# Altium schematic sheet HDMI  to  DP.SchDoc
size A2
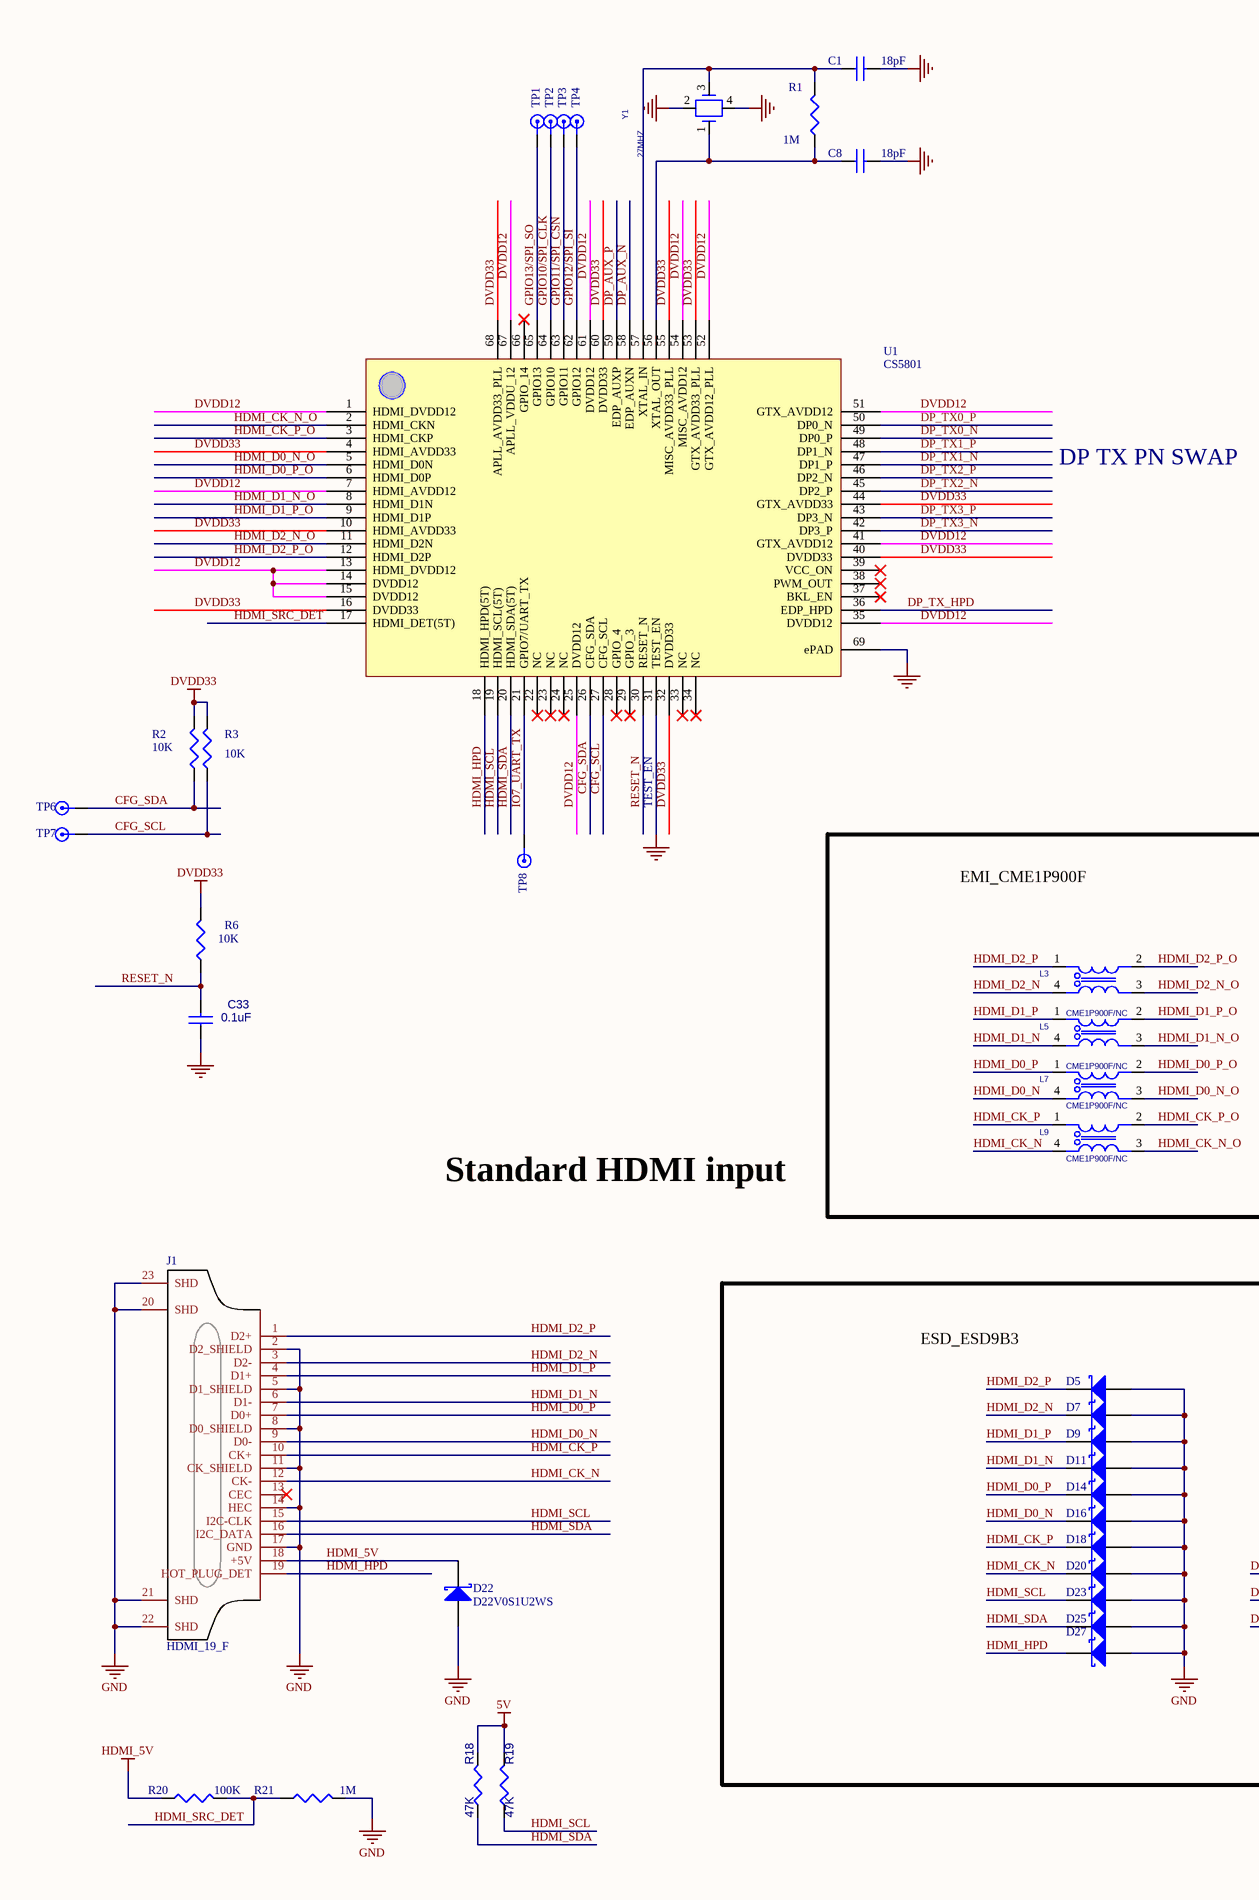
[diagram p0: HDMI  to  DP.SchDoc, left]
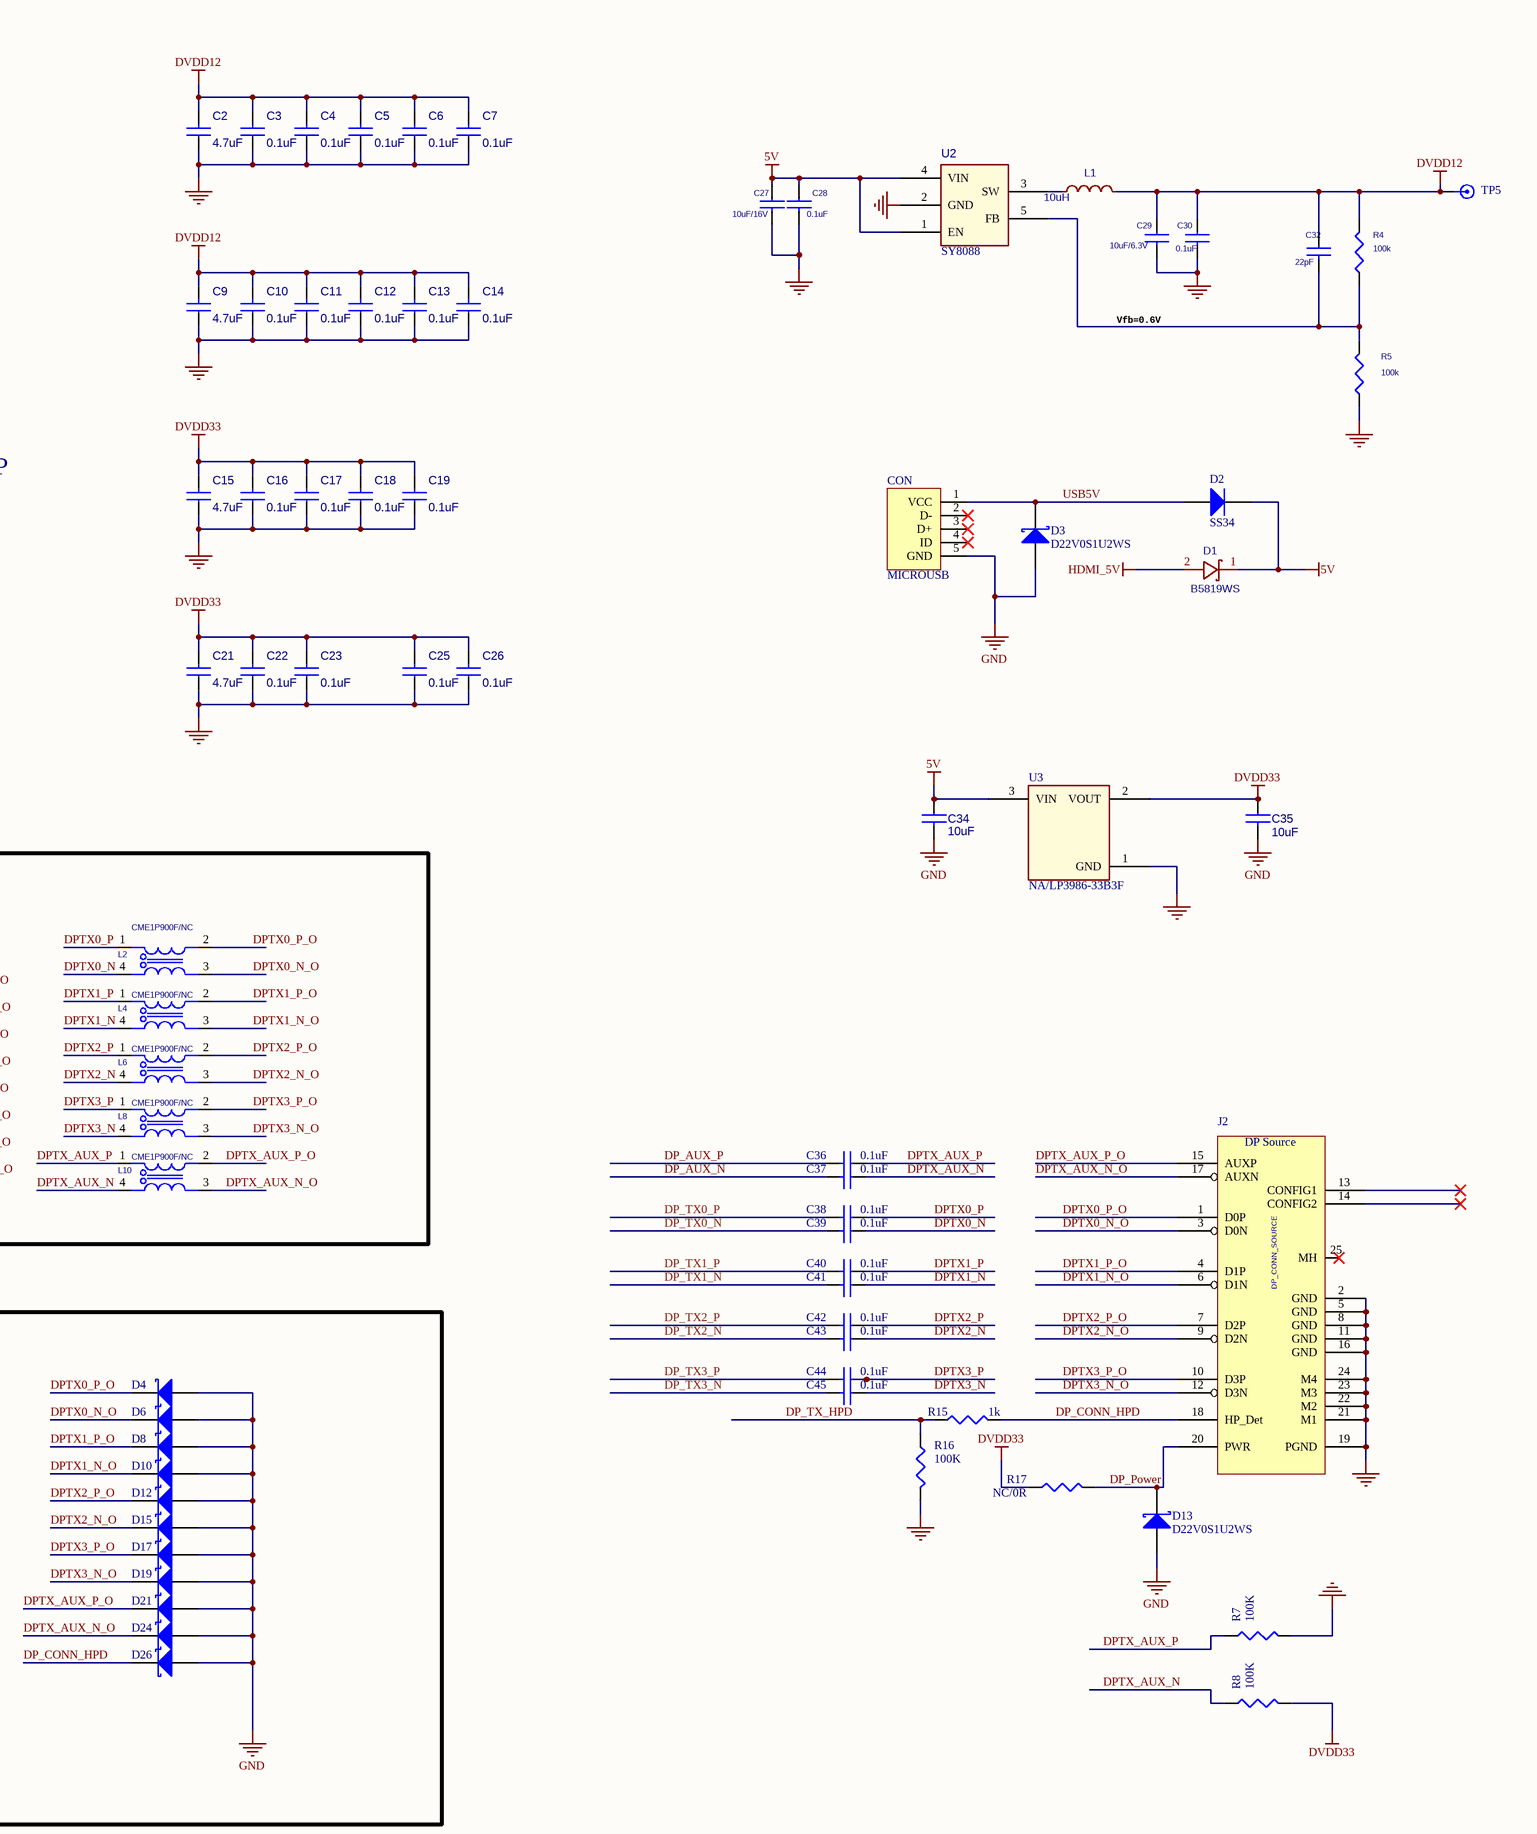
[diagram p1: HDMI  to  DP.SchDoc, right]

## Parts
C1  18pF  [0402/1005 C2]
C2  4.7uF  [0603/1608 C2]
C3  0.1uF  [0402/1005 C2]
C4  0.1uF  [0402/1005 C2]
C5  0.1uF  [0402/1005 C2]
C6  0.1uF  [0402/1005 C2]
C7  0.1uF  [0402/1005 C2]
C8  18pF  [0402/1005 C2]
C9  4.7uF  [0603/1608 C2]
C10  0.1uF  [0402/1005 C2]
C11  0.1uF  [0402/1005 C2]
C12  0.1uF  [0402/1005 C2]
C13  0.1uF  [0402/1005 C2]
C14  0.1uF  [0402/1005 C2]
C15  4.7uF  [0603/1608 C2]
C16  0.1uF  [0402/1005 C2]
C17  0.1uF  [0402/1005 C2]
C18  0.1uF  [0402/1005 C2]
C19  0.1uF  [0402/1005 C2]
C21  4.7uF  [0603/1608 C2]
C22  0.1uF  [0402/1005 C2]
C23  0.1uF  [0402/1005 C2]
C25  0.1uF  [0402/1005 C2]
C26  0.1uF  [0402/1005 C2]
C27  10uF/16V  [0603/1608 C2]
C28  0.1uF  [0402/1005 C2]
C29  10uF/6.3V  [0603/1608 C2]
C30  0.1uF  [0402/1005 C2]
C32  22pF  [0402/1005 C2]
C33  0.1uF  [0402/1005 C2]
C34  10uF  [0603/1608 C2]
C35  10uF  [0603/1608 C2]
C36  0.1uF  [0402/1005 C2]
C37  0.1uF  [0402/1005 C2]
C38  0.1uF  [0402/1005 C2]
C39  0.1uF  [0402/1005 C2]
C40  0.1uF  [0402/1005 C2]
C41  0.1uF  [0402/1005 C2]
C42  0.1uF  [0402/1005 C2]
C43  0.1uF  [0402/1005 C2]
C44  0.1uF  [0402/1005 C2]
C45  0.1uF  [0402/1005 C2]
CON  MICROUSB  [USB-MF-S1-180]
D1  B5819WS  [5819]
D2  SS34  [SMA_L4.4-W2.8-LS5.4-R-RD]
D3  D22V0S1U2WS  [SOD-323]
D4  Diode 18TQ045  [SOD-923_L0.8-W0.6-LS1.0-BI]  (value not drawn)
D5  Diode 18TQ045  [SOD-923_L0.8-W0.6-LS1.0-BI]  (value not drawn)
D6  Diode 18TQ045  [SOD-923_L0.8-W0.6-LS1.0-BI]  (value not drawn)
D7  Diode 18TQ045  [SOD-923_L0.8-W0.6-LS1.0-BI]  (value not drawn)
D8  Diode 18TQ045  [SOD-923_L0.8-W0.6-LS1.0-BI]  (value not drawn)
D9  Diode 18TQ045  [SOD-923_L0.8-W0.6-LS1.0-BI]  (value not drawn)
D10  Diode 18TQ045  [SOD-923_L0.8-W0.6-LS1.0-BI]  (value not drawn)
D11  Diode 18TQ045  [SOD-923_L0.8-W0.6-LS1.0-BI]  (value not drawn)
D12  Diode 18TQ045  [SOD-923_L0.8-W0.6-LS1.0-BI]  (value not drawn)
D13  D22V0S1U2WS  [SOD-923_L0.8-W0.6-LS1.0-BI]
D14  Diode 18TQ045  [SOD-923_L0.8-W0.6-LS1.0-BI]  (value not drawn)
D15  Diode 18TQ045  [SOD-923_L0.8-W0.6-LS1.0-BI]  (value not drawn)
D16  Diode 18TQ045  [SOD-923_L0.8-W0.6-LS1.0-BI]  (value not drawn)
D17  Diode 18TQ045  [SOD-923_L0.8-W0.6-LS1.0-BI]  (value not drawn)
D18  Diode 18TQ045  [SOD-923_L0.8-W0.6-LS1.0-BI]  (value not drawn)
D19  Diode 18TQ045  [SOD-923_L0.8-W0.6-LS1.0-BI]  (value not drawn)
D20  Diode 18TQ045  [SOD-923_L0.8-W0.6-LS1.0-BI]  (value not drawn)
D21  Diode 18TQ045  [SOD-923_L0.8-W0.6-LS1.0-BI]  (value not drawn)
D22  D22V0S1U2WS  [SOD-323]
D23  Diode 18TQ045  [SOD-923_L0.8-W0.6-LS1.0-BI]  (value not drawn)
D24  Diode 18TQ045  [SOD-923_L0.8-W0.6-LS1.0-BI]  (value not drawn)
D25  Diode 18TQ045  [SOD-923_L0.8-W0.6-LS1.0-BI]  (value not drawn)
D26  Diode 18TQ045  [SOD-923_L0.8-W0.6-LS1.0-BI]  (value not drawn)
D27  Diode 18TQ045  [SOD-923_L0.8-W0.6-LS1.0-BI]  (value not drawn)
J1  HDMI_19_F  [HDMI-G]
J2  DP_CONN_SOURCE  [DP-20-J]
L1  10uH  [SWPA252012S]
L2  CME1P900F/NC  [FLT4-0.6-1.3X1.3]
L3  CME1P900F/NC  [FLT4-0.6-1.3X1.3]
L4  CME1P900F/NC  [FLT4-0.6-1.3X1.3]
L5  CME1P900F/NC  [FLT4-0.6-1.3X1.3]
L6  CME1P900F/NC  [FLT4-0.6-1.3X1.3]
L7  CME1P900F/NC  [FLT4-0.6-1.3X1.3]
L8  CME1P900F/NC  [FLT4-0.6-1.3X1.3]
L9  CME1P900F/NC  [FLT4-0.6-1.3X1.3]
L10  CME1P900F/NC  [FLT4-0.6-1.3X1.3]
R1  1M  [0402/1005 R2]
R2  10K  [0402/1005 R2]
R3  10K  [0402/1005 R2]
R4  100k  [0402/1005 R2]
R5  100k  [0402/1005 R2]
R6  10K  [0402/1005 R2]
R7  100K  [0402/1005 R2]
R8  100K  [0402/1005 R2]
R15  1k  [0402/1005 R2]
R16  100K  [0402/1005 R2]
R17  NC/0R  [0402/1005 R2]
R18  47K  [0402/1005 R2]
R19  47K  [0402/1005 R2]
R20  100K  [0402/1005 R2]
R21  1M  [0402/1005 R2]
TP1  TEST_POINT  [PAD]  (value not drawn)
TP2  TEST_POINT  [PAD]  (value not drawn)
TP3  TEST_POINT  [PAD]  (value not drawn)
TP4  TEST_POINT  [PAD]  (value not drawn)
TP5  TEST_POINT  [PAD]  (value not drawn)
TP6  TEST_POINT  [PAD]  (value not drawn)
TP7  TEST_POINT  [PAD]  (value not drawn)
TP8  TEST_POINT  [PAD]  (value not drawn)
U1  CS5801  [QFN68]
U2  SY8088  [SOT23-5L]
U3  NA/LP3986-33B3F  [SOT-123-B]
Y1  27MHZ  [SMD3225]

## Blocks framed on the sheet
EMI_CME1P900F: L2-L10
ESD_ESD9B3: D4-D12 D14-D21 D23-D27

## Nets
5V: C27.1 C28.1 C34.1 D1.1(K) D2.2(K) R18.2 R19.2 U2.1(EN) U2.4(VIN) U3.3(VIN)
DVDD12: C2.2 C3.2 C4.2 C5.2 C6.2 C7.2 C9.2 C10.2 C11.2 C12.2 C13.2 C14.2 C29.1 C30.1 C32.1 L1.2 R4.2 TP5.1 U1.1(HDMI_DVDD12) U1.7(HDMI_AVDD12) U1.13(HDMI_DVDD12) U1.14(DVDD12) U1.15(DVDD12) U1.25(DVDD12) U1.35(DVDD12) U1.41(GTX_AVDD12) U1.51(GTX_AVDD12) U1.52(GTX_AVDD12_PLL) U1.54(MISC_AVDD12) U1.61(DVDD12) U1.67(APLL_VDDU_12)
DVDD33: C15.2 C16.2 C17.2 C18.2 C19.2 C21.2 C22.2 C23.2 C25.2 C26.2 C35.1 R2.1 R3.1 R6.1 R8.2 R17.2 U1.4(HDMI_AVDD33) U1.10(HDMI_AVDD33) U1.16(DVDD33) U1.32(DVDD33) U1.40(DVDD33) U1.44(GTX_AVDD33) U1.53(GTX_AVDD33_PLL) U1.55(MISC_AVDD33_PLL) U1.60(DVDD33) U1.68(APLL_AVDD33_PLL) U3.2(VOUT)
GND: C1.2 C2.1 C3.1 C4.1 C5.1 C6.1 C7.1 C8.2 C9.1 C10.1 C11.1 C12.1 C13.1 C14.1 C15.1 C16.1 C17.1 C18.1 C19.1 C21.1 C22.1 C23.1 C25.1 C26.1 C27.2 C28.2 C29.2 C30.2 C33.1 C34.2 C35.2 CON.5(GND) D3.3(A) D4.3(A) D5.3(A) D6.3(A) D7.3(A) D8.3(A) D9.3(A) D10.3(A) D11.3(A) D12.3(A) D13.3(A) D14.3(A) D15.3(A) D16.3(A) D17.3(A) D18.3(A) D19.3(A) D20.3(A) D21.3(A) D22.3(A) D23.3(A) D24.3(A) D25.3(A) D26.3(A) D27.3(A) J1.2(D2_SHIELD) J1.5(D1_SHIELD) J1.8(D0_SHIELD) J1.11(CK_SHIELD) J1.14(HEC) J1.17(GND) J1.20(SHD) J1.21(SHD) J1.22(SHD) J1.23(SHD) J2.2(GND) J2.5(GND) J2.8(GND) J2.11(GND) J2.16(GND) J2.19(PGND) J2.21(M1) J2.22(M2) J2.23(M3) J2.24(M4) R5.1 R7.2 R16.2 R21.2 U1.31(TEST_EN) U1.69(ePAD) U2.2(GND) U3.1(GND) Y1.2(GND) Y1.4(VDC)
HDMI_5V: D1.2(A) D22.1(K) J1.18(+5V) R20.1
CFG_SCL: R3.2 TP7.1 U1.27(CFG_SCL)
CFG_SDA: R2.2 TP6.1 U1.26(CFG_SDA)
DP_AUX_N: C37.2 U1.58(EDP_AUXN)
DP_AUX_P: C36.2 U1.59(EDP_AUXP)
DP_CONN_HPD: D26.1(K) J2.18(HP_Det) R15.2
DP_Power: D13.1(K) J2.20(PWR) R17.1
DP_TX0_N: C39.2 U1.49(DP0_P)
DP_TX0_P: C38.2 U1.50(DP0_N)
DP_TX1_N: C41.2 U1.47(DP1_P)
DP_TX1_P: C40.2 U1.48(DP1_N)
DP_TX2_N: C43.2 U1.45(DP2_P)
DP_TX2_P: C42.2 U1.46(DP2_N)
DP_TX3_N: C45.2 U1.42(DP3_P)
DP_TX3_P: C44.2 U1.43(DP3_N)
DP_TX_HPD: R15.1 R16.1 U1.36(EDP_HPD)
DPTX0_N: C39.1 L2.4
DPTX0_N_O: D6.1(K) J2.3(D0N) L2.3
DPTX0_P: C38.1 L2.1
DPTX0_P_O: D4.1(K) J2.1(D0P) L2.2
DPTX1_N: C41.1 L4.4
DPTX1_N_O: D10.1(K) J2.6(D1N) L4.3
DPTX1_P: C40.1 L4.1
DPTX1_P_O: D8.1(K) J2.4(D1P) L4.2
DPTX2_N: C43.1 L6.4
DPTX2_N_O: D15.1(K) J2.9(D2N) L6.3
DPTX2_P: C42.1 L6.1
DPTX2_P_O: D12.1(K) J2.7(D2P) L6.2
DPTX3_N: C45.1 L8.4
DPTX3_N_O: D19.1(K) J2.12(D3N) L8.3
DPTX3_P: C44.1 L8.1
DPTX3_P_O: D17.1(K) J2.10(D3P) L8.2
DPTX_AUX_N: C37.1 L10.4 R8.1
DPTX_AUX_N_O: D24.1(K) J2.17(AUXN) L10.3
DPTX_AUX_P: C36.1 L10.1 R7.1
DPTX_AUX_P_O: D21.1(K) J2.15(AUXP) L10.2
GPIO10/SPI_CLK: TP2.1 U1.64(GPIO10)
GPIO11/SPI_CSN: TP3.1 U1.63(GPIO11)
GPIO12/SPI_SI: TP4.1 U1.62(GPIO12)
GPIO13/SPI_SO: TP1.1 U1.65(GPIO13)
HDMI_CK_N: D20.1(K) J1.12(CK-) L9.4
HDMI_CK_N_O: L9.3 U1.2(HDMI_CKN)
HDMI_CK_P: D18.1(K) J1.10(CK+) L9.1
HDMI_CK_P_O: L9.2 U1.3(HDMI_CKP)
HDMI_D0_N: D16.1(K) J1.9(D0-) L7.4
HDMI_D0_N_O: L7.3 U1.5(HDMI_D0N)
HDMI_D0_P: D14.1(K) J1.7(D0+) L7.1
HDMI_D0_P_O: L7.2 U1.6(HDMI_D0P)
HDMI_D1_N: D11.1(K) J1.6(D1-) L5.4
HDMI_D1_N_O: L5.3 U1.8(HDMI_D1N)
HDMI_D1_P: D9.1(K) J1.4(D1+) L5.1
HDMI_D1_P_O: L5.2 U1.9(HDMI_D1P)
HDMI_D2_N: D7.1(K) J1.3(D2-) L3.4
HDMI_D2_N_O: L3.3 U1.11(HDMI_D2N)
HDMI_D2_P: D5.1(K) J1.1(D2+) L3.1
HDMI_D2_P_O: L3.2 U1.12(HDMI_D2P)
HDMI_HPD: D27.1(K) J1.19(HOT_PLUG_DET) U1.18(HDMI_HPD(5T))
HDMI_SCL: D23.1(K) J1.15(I2C-CLK) R19.1 U1.19(HDMI_SCL(5T))
HDMI_SDA: D25.1(K) J1.16(I2C_DATA) R18.1 U1.20(HDMI_SDA(5T))
HDMI_SRC_DET: R20.2 R21.1 U1.17(HDMI_DET(5T))
IO7_UART_TX: TP8.1 U1.21(GPIO7/UART_TX)
RESET_N: C33.2 R6.2 U1.30(RESET_N)
USB5V: CON.1(VCC) D2.1(A) D3.1(K)
NetC1_1: C1.1 R1.1 U1.57(XTAL_IN) Y1.3(OUT)
NetC8_1: C8.1 R1.2 U1.56(XTAL_OUT) Y1.1(NC)
NetC32_2: C32.2 R4.1 R5.2 U2.5(FB)
NetL1_1: L1.1 U2.3(SW)

Not connected (* = marked no-connect by the designer): CON 2(D-)* 3(D+)* 4(ID)*; J1 13(CEC)*; J2 13(CONFIG1)* 14(CONFIG2)* 25(MH)*; U1 22(NC)* 23(NC)* 24(NC)* 28(GPIO_4)* 29(GPIO_3)* 33(NC)* 34(NC)* 37(BKL_EN)* 38(PWM_OUT)* 39(VCC_ON)* 66(GPIO_14)*

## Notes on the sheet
- Vfb=0.6V
- DP TX PN SWAP
- TEST_EN
- Standard HDMI input

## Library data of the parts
C1-C19 C21-C23 C25-C30 C32-C45 = CAP NP
D1 = B5819WS_C22624: BOM_Manufacturer: CJ; SMT Type: Extend
D2 = Diode 1N4001: 1 Amp General Purpose Rectifier
D3-D27 = Diode 18TQ045: Schottky Rectifier; Note: Terminal 2 is the TAB and is electrically connected to the cathode
J1 = HDMI_F
J2 = DP_CONN_SOURCE_0_1: 0_MANUFACTURER: Molex; 0_PARTNUM: 47272-0001
L1 = 10uH: BOM_Manufacturer: Sunlord; BOM_Manufacturer Part: WPN3012H100MT; nameAlias: Inductance
L2-L10 = CHOKE-DLW21S_1_Dup1: Part Number: 99G23-051695; QUAN: 0; Qualify: YES; Dsc8: MURATA; Dsc7: 2.0mm*1.2mm*1.2mm; Dsc6: 4PAD; Dsc5: 280mA; Dsc4: 90 OHM∮25%; Dsc3: SMD; Dsc2: DLW21SN900HQ2; Dsc1: CHOKE COIL; approval status: PL; 弧: CHOKE COIL DLW21SN900HQ2 SMD 9; ID: 17,777
R1-R6 = R0603: 0_MANUFACTURER: Panasonic; 0_PARTNUM: ERJ-3GEYJ105V
R7 R8 R16 = 0603 47K Ohm 5%: 0_MANUFACTURER: Rohm; 0_PARTNUM: MCR03EZPJ473
R15 R17 = R0603: 0_MANUFACTURER: Panasonic; 0_PARTNUM: ERJ-3GEYJ105V; PartDescription: LF RESISTOR 200K 1% 1/16W EIA(0402); GroupName: DNI; TC: 316
R18 R19 = R
R20 = R0603: 0_MANUFACTURER: Panasonic; 0_PARTNUM: ERJ-3GEYJ105V; PartDescription: LF RESISTOR 200K 1% 1/16W EIA(0402); GroupName: DNI
R21 = R0603: 0_MANUFACTURER: Panasonic; 0_PARTNUM: ERJ-3GEYJ105V; PartDescription: LF RESISTOR 5.1M 5% 1/16W EIA(0603); GroupName: COMMON
TP1-TP8 = TEST_POINT: Last Edit By: IHA; CLASS: IO
U2 = AP3406K-ADJTRG1_0
U3 = LDO_3Pin
Y1 = CRYSTAL_SMD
